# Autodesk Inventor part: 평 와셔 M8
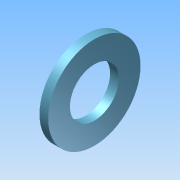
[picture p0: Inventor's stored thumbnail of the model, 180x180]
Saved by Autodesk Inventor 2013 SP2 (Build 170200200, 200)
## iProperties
Created: 2025-10
Part Number: 평 와셔 M8
Material: Generic
Document SubType Name: Modeling
Designer: 601
Density: 1 g/cm^3
변환 표준: STEP AP214IS
전처리기: Build: 200, Release: 2013 SP2 Update 6 - Date: Thu 07/17/2014
전송 단위: 밀리미터
불확실성: 0.01
Author: 601
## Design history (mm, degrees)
node "평 와셔 M81"
body "Solid1"
node "기준1"
